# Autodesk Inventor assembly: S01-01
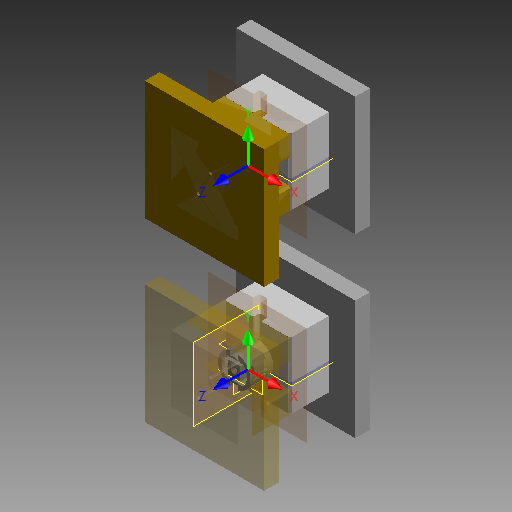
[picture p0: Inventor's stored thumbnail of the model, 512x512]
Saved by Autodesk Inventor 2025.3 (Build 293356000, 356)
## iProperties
Part Number: S01-01
Document SubType Name: Sestava
Designer: Patrik
Description: Tvarové vložky
Author: Patrik
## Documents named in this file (6)
- C:\Users\Patrik\Documents\Skola\Bakalarska prace\Prakticka cast\Sestava - mold design_MODEL - mk4 Blenddoor Tab v4_2_LY.iam
- C:\Users\Patrik\Documents\Skola\Bakalarska prace\Prakticka cast\Sestava - mold design_MODEL - mk4 Blenddoor Tab v4_2_PZ.iam
- C:\Users\Patrik\Documents\Skola\Bakalarska prace\Prakticka cast\Sestava - mold design_MODEL - mk4 Blenddoor Tab v4_2_CV_2.ipt
- C:\Users\Patrik\Documents\Skola\Bakalarska prace\Prakticka cast\Sestava - mold design_MODEL - mk4 Blenddoor Tab v4_2_CV_1.ipt
- C:\Users\Patrik\Documents\Skola\Bakalarska prace\Prakticka cast\Sestava - mold design_MODEL - mk4 Blenddoor Tab v4_2_CR_2.ipt
- C:\Users\Patrik\Documents\Skola\Bakalarska prace\Prakticka cast\Sestava - mold design_MODEL - mk4 Blenddoor Tab v4_2_CR_1.ipt
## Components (6 placed, 5 different names)
1. Sestava - mold design_MODEL - mk4 Blenddoor Tab v4_2_PZ:1 [sub-assembly] — Stejný směr:1, Stejný směr:2, Stejný směr:3, Stejný směr:7, Stejný směr:8, Stejný směr:9, Stejný směr:13, Stejný směr:14, Stejný směr:15
2. Sestava - mold design_MODEL - mk4 Blenddoor Tab v4_2_PZ:2 [sub-assembly] — Stejný směr:4, Stejný směr:5, Stejný směr:6, Stejný směr:10, Stejný směr:11, Stejný směr:12, Stejný směr:16, Stejný směr:17, Stejný směr:18
3. Sestava - mold design_MODEL - mk4 Blenddoor Tab v4_2_CV_1:1 — Stejný směr:7, Stejný směr:8, Stejný směr:9
4. Sestava - mold design_MODEL - mk4 Blenddoor Tab v4_2_CV_2:1 — Stejný směr:10, Stejný směr:11, Stejný směr:12
5. Sestava - mold design_MODEL - mk4 Blenddoor Tab v4_2_CR_1:1 — Stejný směr:13, Stejný směr:14, Stejný směr:15
6. Sestava - mold design_MODEL - mk4 Blenddoor Tab v4_2_CR_2:1 — Stejný směr:16, Stejný směr:17, Stejný směr:18
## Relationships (18: Flush 18)
- Stejný směr:1 [Flush]: Sestava - mold design_MODEL - mk4 Blenddoor Tab v4_2_PZ:1
- Stejný směr:2 [Flush]: Sestava - mold design_MODEL - mk4 Blenddoor Tab v4_2_PZ:1
- Stejný směr:3 [Flush]: Sestava - mold design_MODEL - mk4 Blenddoor Tab v4_2_PZ:1
- Stejný směr:4 [Flush]: Sestava - mold design_MODEL - mk4 Blenddoor Tab v4_2_PZ:2
- Stejný směr:5 [Flush]: Sestava - mold design_MODEL - mk4 Blenddoor Tab v4_2_PZ:2
- Stejný směr:6 [Flush]: Sestava - mold design_MODEL - mk4 Blenddoor Tab v4_2_PZ:2
- Stejný směr:7 [Flush]: Sestava - mold design_MODEL - mk4 Blenddoor Tab v4_2_PZ:1 ↔ Sestava - mold design_MODEL - mk4 Blenddoor Tab v4_2_CV_1:1
- Stejný směr:8 [Flush]: Sestava - mold design_MODEL - mk4 Blenddoor Tab v4_2_PZ:1 ↔ Sestava - mold design_MODEL - mk4 Blenddoor Tab v4_2_CV_1:1
- Stejný směr:9 [Flush]: Sestava - mold design_MODEL - mk4 Blenddoor Tab v4_2_PZ:1 ↔ Sestava - mold design_MODEL - mk4 Blenddoor Tab v4_2_CV_1:1
- Stejný směr:10 [Flush]: Sestava - mold design_MODEL - mk4 Blenddoor Tab v4_2_PZ:2 ↔ Sestava - mold design_MODEL - mk4 Blenddoor Tab v4_2_CV_2:1
- Stejný směr:11 [Flush]: Sestava - mold design_MODEL - mk4 Blenddoor Tab v4_2_PZ:2 ↔ Sestava - mold design_MODEL - mk4 Blenddoor Tab v4_2_CV_2:1
- Stejný směr:12 [Flush]: Sestava - mold design_MODEL - mk4 Blenddoor Tab v4_2_PZ:2 ↔ Sestava - mold design_MODEL - mk4 Blenddoor Tab v4_2_CV_2:1
- Stejný směr:13 [Flush]: Sestava - mold design_MODEL - mk4 Blenddoor Tab v4_2_PZ:1 ↔ Sestava - mold design_MODEL - mk4 Blenddoor Tab v4_2_CR_1:1
- Stejný směr:14 [Flush]: Sestava - mold design_MODEL - mk4 Blenddoor Tab v4_2_PZ:1 ↔ Sestava - mold design_MODEL - mk4 Blenddoor Tab v4_2_CR_1:1
- Stejný směr:15 [Flush]: Sestava - mold design_MODEL - mk4 Blenddoor Tab v4_2_PZ:1 ↔ Sestava - mold design_MODEL - mk4 Blenddoor Tab v4_2_CR_1:1
- Stejný směr:16 [Flush]: Sestava - mold design_MODEL - mk4 Blenddoor Tab v4_2_PZ:2 ↔ Sestava - mold design_MODEL - mk4 Blenddoor Tab v4_2_CR_2:1
- Stejný směr:17 [Flush]: Sestava - mold design_MODEL - mk4 Blenddoor Tab v4_2_PZ:2 ↔ Sestava - mold design_MODEL - mk4 Blenddoor Tab v4_2_CR_2:1
- Stejný směr:18 [Flush]: Sestava - mold design_MODEL - mk4 Blenddoor Tab v4_2_PZ:2 ↔ Sestava - mold design_MODEL - mk4 Blenddoor Tab v4_2_CR_2:1
